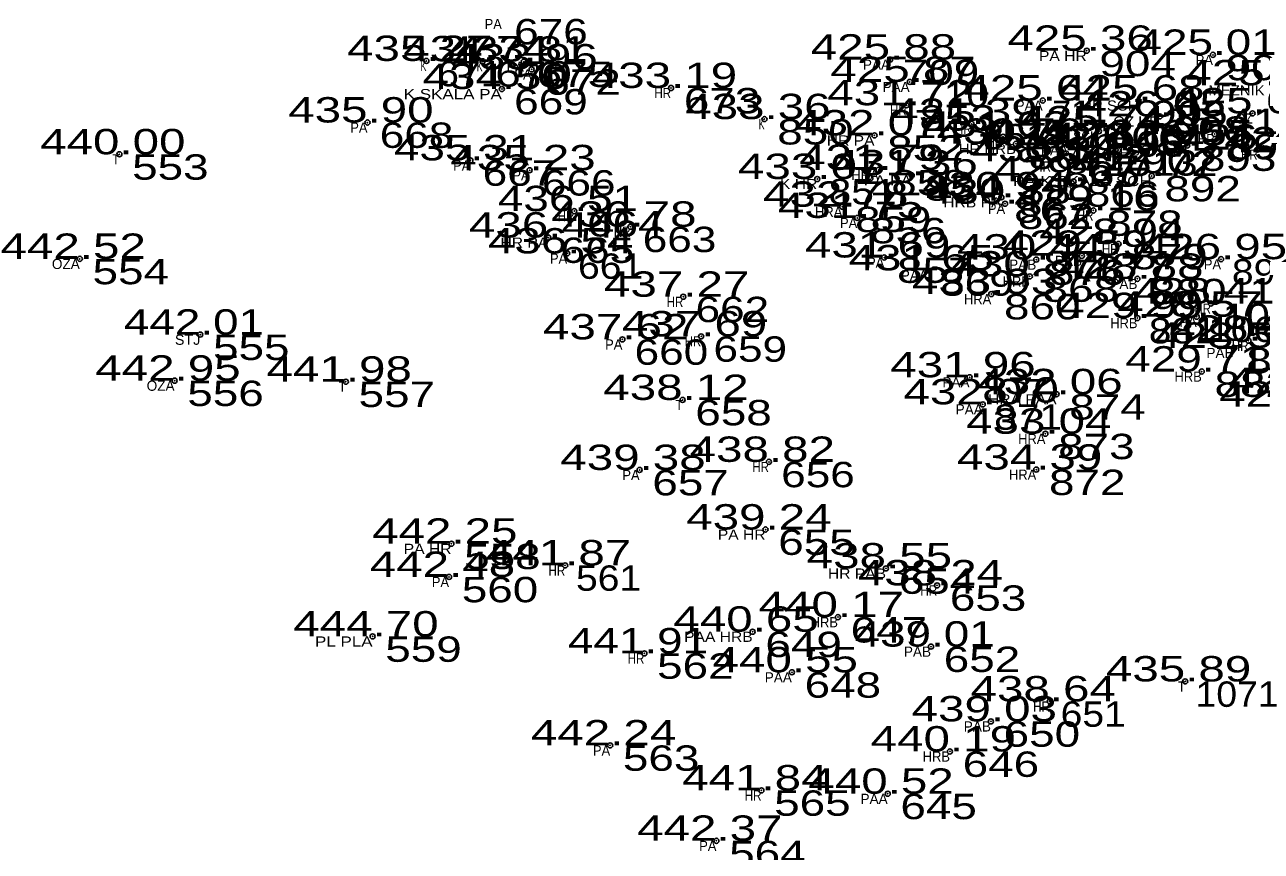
# Model space of a CAD drawing. Extents: x -639390 to -639074, y -1138747 to -1138358.
# Drawn here: x -639157.96 to -639121.42, y -1138697.01 to -1138672.58 of the extents above; entities that cross this region are included whole.
import ezdxf
from ezdxf.enums import TextEntityAlignment as Align

# ---------------------------------------------------------------- set-up
doc = ezdxf.new("R2010")
doc.units = 0
doc.header["$LTSCALE"] = 0.3
doc.header["$PDMODE"] = 32
doc.header["$PDSIZE"] = 0.15
for name, color, linetype in [('11', 7, 'Continuous'), ('12', 7, 'Continuous'), ('13', 7, 'Continuous'), ('57', 7, 'Continuous')]:
    doc.layers.add(name, color=color, linetype=linetype)

msp = doc.modelspace()

# ---------------------------------------------------------------- linework, layer by layer
at = {"layer": '11'}
for p in [(-639146.09, -1138673.65), (-639144.43, -1138673.66), (-639132.39, -1138673.61), (-639126.58, -1138673.35), (-639122.85, -1138673.47), (-639143.21, -1138673.67), (-639142.98, -1138673.9), (-639131.81, -1138674.27), (-639143.86, -1138674.48), (-639138.86, -1138674.45), (-639131.9, -1138674.96), (-639127.88, -1138674.82), (-639125.05, -1138674.82), (-639147.83, -1138675.47), (-639136.1, -1138675.37), (-639124.42, -1138675.29), (-639121.68, -1138675.2), (-639132.85, -1138675.85), (-639129.98, -1138675.51), (-639126.22, -1138675.73), (-639122.8, -1138675.81), (-639129.05, -1138675.89), (-639128.67, -1138676.1), (-639127.13, -1138676.14), (-639123.61, -1138676.15), (-639155.16, -1138676.41), (-639125.65, -1138676.29), (-639125.34, -1138676.22), (-639121.53, -1138676.27), (-639144.79, -1138676.59), (-639143.04, -1138676.88), (-639132.73, -1138676.87), (-639127.64, -1138676.62), (-639134.54, -1138677.14), (-639131.75, -1138677.03), (-639126.97, -1138677.21), (-639124.66, -1138677.05), (-639133.8, -1138677.96), (-639129.1, -1138677.68), (-639128.99, -1138677.87), (-639141.72, -1138678.09), (-639133.36, -1138678.29), (-639126.38, -1138678.07), (-639140.06, -1138678.55), (-639142.49, -1138678.87), (-639125.64, -1138679.06), (-639156.33, -1138679.5), (-639141.93, -1138679.34), (-639132.56, -1138679.46), (-639126.72, -1138679.41), (-639131.27, -1138679.84), (-639128.07, -1138679.52), (-639122.61, -1138679.51), (-639128.26, -1138680.02), (-639125.08, -1138680.09), (-639129.4, -1138680.54), (-639138.5, -1138680.62), (-639122.91, -1138680.82), (-639125.08, -1138681.25), (-639123.33, -1138681.21), (-639152.77, -1138681.74), (-639140.3, -1138681.88), (-639137.97, -1138681.79), (-639121.8, -1138681.92), (-639122.24, -1138682.13), (-639153.53, -1138683.1), (-639148.47, -1138683.13), (-639130.04, -1138683), (-639123.18, -1138682.83), (-639127.47, -1138683.5), (-639138.52, -1138683.67), (-639129.65, -1138683.8), (-639127.8, -1138684.67), (-639135.97, -1138685.5), (-639139.79, -1138685.74), (-639128.07, -1138685.73), (-639136.07, -1138687.5), (-639145.35, -1138687.92), (-639141.99, -1138688.56), (-639145.42, -1138688.9), (-639132.51, -1138688.65), (-639131, -1138689.15), (-639133.93, -1138690.09), (-639147.68, -1138690.66), (-639136.45, -1138690.52), (-639139.65, -1138691.16), (-639131.18, -1138690.96), (-639135.29, -1138691.72), (-639123.67, -1138691.99), (-639127.67, -1138692.58), (-639129.41, -1138693.17), (-639140.66, -1138693.88), (-639130.62, -1138694.06), (-639136.19, -1138695.21), (-639132.46, -1138695.31), (-639137.52, -1138696.7)]:
    msp.add_point(p, dxfattribs=at)

# ---------------------------------------------------------------- texts
at = {"layer": '12'}
for s, width, p in [('425.88 ', 1.4, (-639132.39, -1138673.61)), ('425.36 ', 1.4, (-639126.579, -1138673.35)), ('425.01 ', 1.35, (-639122.849, -1138673.47)), ('435.27 ', 1.4, (-639146.09, -1138673.65)), ('434.74 ', 1.4, (-639144.43, -1138673.66)), ('433.81 ', 1.35, (-639143.209, -1138673.67)), ('433.96 ', 1.4, (-639142.979, -1138673.9)), ('425.87 ', 1.4, (-639131.81, -1138674.27)), ('434.50 ', 1.4, (-639143.86, -1138674.48)), ('433.19 ', 1.4, (-639138.86, -1138674.45)), ('425.18 ', 1.4, (-639121.32, -1138674.37)), ('431.72 ', 1.4, (-639131.9, -1138674.96)), ('425.64 ', 1.4, (-639127.88, -1138674.82)), ('425.68 ', 1.4, (-639125.05, -1138674.82)), ('433.36 ', 1.4, (-639136.099, -1138675.37)), ('426.05 ', 1.4, (-639124.42, -1138675.29)), ('425.62 ', 1.4, (-639121.68, -1138675.2)), ('435.90 ', 1.4, (-639147.83, -1138675.47)), ('431.39 ', 1.4, (-639129.98, -1138675.51)), ('425.74 ', 1.4, (-639126.22, -1138675.73)), ('432.07 ', 1.4, (-639132.85, -1138675.85)), ('431.03 ', 1.4, (-639129.05, -1138675.89)), ('430.76 ', 1.4, (-639128.669, -1138676.1)), ('425.78 ', 1.4, (-639127.13, -1138676.14)), ('426.55 ', 1.4, (-639123.61, -1138676.15)), ('426.41 ', 1.35, (-639122.799, -1138675.81)), ('440.00 ', 1.4, (-639155.16, -1138676.41)), ('426.06 ', 1.4, (-639125.649, -1138676.29)), ('426.09 ', 1.4, (-639125.34, -1138676.22)), ('426.49 ', 1.4, (-639121.53, -1138676.27)), ('425.63 ', 1.4, (-639120.17, -1138676.35)), ('435.31 ', 1.35, (-639144.789, -1138676.59)), ('435.23 ', 1.4, (-639143.04, -1138676.88)), ('431.79 ', 1.4, (-639132.73, -1138676.87)), ('430.14 ', 1.4, (-639127.64, -1138676.62)), ('433.07 ', 1.4, (-639134.54, -1138677.14)), ('431.36 ', 1.4, (-639131.749, -1138677.03)), ('429.67 ', 1.4, (-639126.97, -1138677.21)), ('426.72 ', 1.4, (-639124.66, -1138677.05)), ('432.78 ', 1.4, (-639133.8, -1138677.96)), ('430.94 ', 1.4, (-639129.1, -1138677.68)), ('430.88 ', 1.4, (-639128.99, -1138677.87)), ('436.51 ', 1.35, (-639141.719, -1138678.09)), ('431.75 ', 1.4, (-639133.36, -1138678.29)), ('429.16 ', 1.4, (-639126.379, -1138678.07)), ('436.78 ', 1.4, (-639140.06, -1138678.55)), ('436.44 ', 1.4, (-639142.49, -1138678.87)), ('428.94 ', 1.4, (-639125.64, -1138679.06)), ('436.54 ', 1.4, (-639141.93, -1138679.34)), ('431.69 ', 1.4, (-639132.56, -1138679.46)), ('429.59 ', 1.4, (-639126.72, -1138679.41)), ('442.52 ', 1.4, (-639156.33, -1138679.5)), ('430.44 ', 1.4, (-639128.07, -1138679.52)), ('426.95 ', 1.4, (-639122.61, -1138679.51)), ('431.65 ', 1.4, (-639131.27, -1138679.84)), ('430.87 ', 1.4, (-639128.26, -1138680.02)), ('428.88 ', 1.4, (-639125.08, -1138680.09)), ('433.93 ', 1.4, (-639129.4, -1138680.54)), ('437.27 ', 1.4, (-639138.5, -1138680.62)), ('428.41 ', 1.35, (-639122.909, -1138680.82)), ('429.99 ', 1.4, (-639125.08, -1138681.25)), ('428.57 ', 1.4, (-639123.33, -1138681.21)), ('442.01 ', 1.35, (-639152.769, -1138681.74)), ('437.62 ', 1.4, (-639140.3, -1138681.88)), ('437.69 ', 1.4, (-639137.97, -1138681.79)), ('428.40 ', 1.4, (-639121.8, -1138681.92)), ('426.87 ', 1.4, (-639119.17, -1138681.79)), ('428.58 ', 1.4, (-639122.24, -1138682.13)), ('442.95 ', 1.4, (-639153.53, -1138683.1)), ('431.96 ', 1.4, (-639130.039, -1138683)), ('429.71 ', 1.35, (-639123.179, -1138682.83)), ('441.98 ', 1.4, (-639148.47, -1138683.13)), ('428.43 ', 1.4, (-639120.05, -1138683.47)), ('438.12 ', 1.4, (-639138.52, -1138683.67)), ('432.07 ', 1.4, (-639129.65, -1138683.8)), ('432.06 ', 1.4, (-639127.469, -1138683.5)), ('428.68 ', 1.4, (-639120.32, -1138683.87)), ('433.04 ', 1.4, (-639127.8, -1138684.67)), ('438.82 ', 1.4, (-639135.97, -1138685.5)), ('439.38 ', 1.4, (-639139.79, -1138685.74)), ('434.39 ', 1.4, (-639128.07, -1138685.73)), ('439.24 ', 1.4, (-639136.07, -1138687.5)), ('442.25 ', 1.4, (-639145.35, -1138687.92)), ('441.87 ', 1.4, (-639141.99, -1138688.56)), ('442.48 ', 1.4, (-639145.42, -1138688.9)), ('438.55 ', 1.4, (-639132.51, -1138688.65)), ('438.24 ', 1.4, (-639131, -1138689.15)), ('440.17 ', 1.4, (-639133.93, -1138690.09)), ('444.70 ', 1.4, (-639147.68, -1138690.66)), ('440.65 ', 1.4, (-639136.45, -1138690.52)), ('439.01 ', 1.35, (-639131.179, -1138690.96)), ('441.91 ', 1.35, (-639139.649, -1138691.16)), ('440.55 ', 1.4, (-639135.29, -1138691.72)), ('435.89 ', 1.4, (-639123.67, -1138691.99)), ('438.64 ', 1.4, (-639127.67, -1138692.58)), ('439.03 ', 1.4, (-639129.41, -1138693.17)), ('442.24 ', 1.4, (-639140.66, -1138693.88)), ('440.19 ', 1.4, (-639130.62, -1138694.06)), ('441.84 ', 1.4, (-639136.19, -1138695.21)), ('440.52 ', 1.4, (-639132.46, -1138695.31)), ('442.37 ', 1.4, (-639137.52, -1138696.7))]:
    msp.add_text(s, height=0.75, dxfattribs=dict(at, width=width)).set_placement(p, align=Align.CENTER)
at = {"layer": '13'}
for s, width, p in [(' 676', 1.3, (-639143.86, -1138673.16)), (' 904', 1.35, (-639126.58, -1138674.1)), (' 903', 1.35, (-639122.85, -1138674.22)), (' 671', 1.15, (-639146.09, -1138674.4)), (' 670', 1.35, (-639144.43, -1138674.41)), (' 675', 1.35, (-639143.21, -1138674.42)), (' 672', 1.35, (-639142.98, -1138674.65)), (' 709', 1.35, (-639132.39, -1138674.36)), (' 710', 1.2, (-639131.81, -1138675.02)), (' 669', 1.3, (-639143.86, -1138675.23)), (' 673', 1.35, (-639138.86, -1138675.2)), (' 853', 1.35, (-639131.9, -1138675.71)), (' 905', 1.35, (-639125.05, -1138675.57)), (' 850', 1.35, (-639136.1, -1138676.12)), (' 908', 1.35, (-639124.42, -1138676.04)), (' 668', 1.3, (-639147.83, -1138676.22)), (' 861', 1.15, (-639129.98, -1138676.26)), (' 906', 1.3, (-639126.22, -1138676.48)), (' 852', 1.35, (-639132.85, -1138676.6)), (' 863', 1.35, (-639129.05, -1138676.64)), (' 864', 1.35, (-639128.67, -1138676.85)), (' 712', 1.2, (-639127.13, -1138676.89)), (' 893', 1.35, (-639123.61, -1138676.9)), (' 894', 1.35, (-639122.8, -1138676.56)), (' 553', 1.35, (-639155.16, -1138677.16)), (' 713', 1.2, (-639125.65, -1138677.04)), (' 907', 1.35, (-639125.34, -1138676.97)), (' 667', 1.3, (-639144.79, -1138677.34)), (' 666', 1.3, (-639143.04, -1138677.63)), (' 858', 1.35, (-639132.73, -1138677.62)), (' 865', 1.35, (-639127.64, -1138677.37)), (' 851', 1.2, (-639134.54, -1138677.89)), (' 854', 1.35, (-639131.75, -1138677.78)), (' 866', 1.3, (-639126.97, -1138677.96)), (' 892', 1.35, (-639124.66, -1138677.8)), (' 859', 1.35, (-639133.8, -1138678.71)), (' 867', 1.35, (-639129.1, -1138678.43)), (' 862', 1.35, (-639128.99, -1138678.62)), (' 664', 1.35, (-639141.72, -1138678.84)), (' 856', 1.35, (-639133.36, -1138679.04)), (' 878', 1.35, (-639126.38, -1138678.82)), (' 663', 1.3, (-639140.06, -1138679.3)), (' 665', 1.3, (-639142.49, -1138679.62)), (' 879', 1.35, (-639125.64, -1138679.81)), (' 661', 1.15, (-639141.93, -1138680.09)), (' 877', 1.35, (-639126.72, -1138680.16)), (' 554', 1.35, (-639156.33, -1138680.25)), (' 857', 1.35, (-639132.56, -1138680.21)), (' 876', 1.35, (-639128.07, -1138680.27)), (' 891', 1.15, (-639122.61, -1138680.26)), (' 869', 1.3, (-639131.27, -1138680.59)), (' 868', 1.35, (-639128.26, -1138680.77)), (' 880', 1.35, (-639125.08, -1138680.84)), (' 662', 1.3, (-639138.5, -1138681.37)), (' 860', 1.35, (-639129.4, -1138681.29)), (' 1068', 1.25, (-639122.91, -1138681.57)), (' 881', 1.2, (-639125.08, -1138682)), (' 1069', 1.2, (-639123.33, -1138681.96)), (' 555', 1.35, (-639152.77, -1138682.49)), (' 660', 1.3, (-639140.3, -1138682.63)), (' 659', 1.3, (-639137.97, -1138682.54)), (' 883', 1.35, (-639122.24, -1138682.88)), (' 870', 1.35, (-639130.04, -1138683.75)), (' 882', 1.35, (-639123.18, -1138683.58)), (' 556', 1.35, (-639153.53, -1138683.85)), (' 557', 1.35, (-639148.47, -1138683.88)), (' 658', 1.35, (-639138.52, -1138684.42)), (' 871', 1.2, (-639129.65, -1138684.55)), (' 874', 1.35, (-639127.47, -1138684.25)), (' 873', 1.35, (-639127.8, -1138685.42)), (' 656', 1.3, (-639135.97, -1138686.25)), (' 657', 1.35, (-639139.79, -1138686.49)), (' 872', 1.35, (-639128.07, -1138686.48)), (' 655', 1.35, (-639136.07, -1138688.25)), (' 558', 1.35, (-639145.35, -1138688.67)), (' 561', 1.15, (-639141.99, -1138689.31)), (' 560', 1.35, (-639145.42, -1138689.65)), (' 654', 1.35, (-639132.51, -1138689.4)), (' 653', 1.35, (-639131, -1138689.9)), (' 647', 1.35, (-639133.93, -1138690.84)), (' 559', 1.35, (-639147.68, -1138691.41)), (' 649', 1.35, (-639136.45, -1138691.27)), (' 652', 1.35, (-639131.18, -1138691.71)), (' 562', 1.35, (-639139.65, -1138691.91)), (' 648', 1.35, (-639135.29, -1138692.47)), (' 1071', 1.1, (-639123.67, -1138692.74)), (' 651', 1.15, (-639127.67, -1138693.33)), (' 650', 1.35, (-639129.41, -1138693.92)), (' 563', 1.35, (-639140.66, -1138694.63)), (' 646', 1.35, (-639130.62, -1138694.81)), (' 565', 1.35, (-639136.19, -1138695.96)), (' 645', 1.35, (-639132.46, -1138696.06)), (' 564', 1.35, (-639137.52, -1138697.45))]:
    msp.add_text(s, height=0.75, dxfattribs=dict(at, width=width)).set_placement(p)
msp.add_text(' 711', height=0.75, dxfattribs=at).set_placement((-639127.88, -1138675.57))
at = {"layer": '57'}
for s, width, p in [('PA', 0.95, (-639143.86, -1138672.71)), ('PA HR', 1.15, (-639126.579, -1138673.65)), ('PA', 0.95, (-639122.85, -1138673.77)), ('K', 0.65, (-639146.089, -1138673.95)), ('K', 0.65, (-639144.429, -1138673.96)), ('PA', 0.95, (-639143.21, -1138673.97)), ('PA', 0.95, (-639142.98, -1138674.2)), ('K SKALA PA', 1.25, (-639143.86, -1138674.78)), ('HR', 0.85, (-639138.859, -1138674.75)), ('MEZNIK', 1.1, (-639121.319, -1138674.67)), ('HR', 0.85, (-639131.899, -1138675.26)), ('HR SCH', 1.1, (-639125.049, -1138675.12)), ('K', 0.65, (-639136.099, -1138675.67)), ('OZ HR', 1.1, (-639124.419, -1138675.59)), ('OZ', 0.9, (-639121.679, -1138675.5)), ('PA', 0.95, (-639147.83, -1138675.77)), ('HR', 0.85, (-639129.979, -1138675.81)), ('SCH', 0.9, (-639126.219, -1138676.03)), ('HR PA', 1.15, (-639132.85, -1138676.15)), ('HR HRB', 1.1, (-639128.669, -1138676.4)), ('HR', 0.85, (-639129.049, -1138676.19)), ('HR', 0.85, (-639122.799, -1138676.11)), ('T', 0.85, (-639155.16, -1138676.71)), ('PAA KA', 1.2, (-639125.65, -1138676.59)), ('SCH', 0.9, (-639125.339, -1138676.52)), ('SCH HR', 1.1, (-639123.609, -1138676.45)), ('HR', 0.85, (-639121.529, -1138676.57)), ('PA', 0.95, (-639144.79, -1138676.89)), ('HRA', 0.95, (-639132.73, -1138677.17)), ('HR', 0.85, (-639127.639, -1138676.92)), ('PA', 0.95, (-639143.04, -1138677.18)), ('K HR', 1.15, (-639134.539, -1138677.44)), ('PA PA', 1.2, (-639131.75, -1138677.33)), ('PA K SKALA SCH', 1.25, (-639124.659, -1138677.35)), ('HR', 0.85, (-639126.969, -1138677.51)), ('HRA', 0.95, (-639133.8, -1138678.26)), ('HRB PA', 1.15, (-639129.1, -1138677.98)), ('PA', 0.95, (-639128.99, -1138678.17)), ('HR', 0.85, (-639141.719, -1138678.39)), ('PA', 0.95, (-639133.36, -1138678.59)), ('HR', 0.85, (-639126.379, -1138678.37)), ('HR', 0.85, (-639140.059, -1138678.85)), ('HR PA', 1.15, (-639142.49, -1138679.17)), ('HR', 0.85, (-639125.639, -1138679.36)), ('PA', 0.95, (-639141.93, -1138679.64)), ('PA', 0.95, (-639132.56, -1138679.76)), ('PA', 0.95, (-639122.61, -1138679.81)), ('HRB', 0.95, (-639128.259, -1138680.32)), ('HR', 0.85, (-639138.499, -1138680.92)), ('HRA', 0.95, (-639129.4, -1138680.84)), ('HR', 0.85, (-639122.909, -1138681.12)), ('HRB', 0.95, (-639125.079, -1138681.55)), ('PA', 0.95, (-639123.33, -1138681.51)), ('STJ', 1.05, (-639152.77, -1138682.04)), ('PA', 0.95, (-639140.3, -1138682.18)), ('HR', 0.85, (-639137.969, -1138682.09)), ('HR', 0.85, (-639121.799, -1138682.22)), ('HRB', 0.95, (-639123.179, -1138683.13)), ('T', 0.85, (-639148.47, -1138683.43)), ('T', 0.85, (-639138.52, -1138683.97)), ('HRA PAA', 1.15, (-639127.47, -1138683.8)), ('HRA', 0.95, (-639127.8, -1138684.97)), ('HR', 0.85, (-639135.969, -1138685.8)), ('PA', 0.95, (-639139.79, -1138686.04)), ('HRA', 0.95, (-639128.07, -1138686.03)), ('PA HR', 1.15, (-639136.069, -1138687.8)), ('PA HR', 1.15, (-639145.349, -1138688.22)), ('HR', 0.85, (-639141.989, -1138688.86)), ('PA', 0.95, (-639145.42, -1138689.2)), ('HR PAB', 1.15, (-639132.509, -1138688.95)), ('HR', 0.85, (-639130.999, -1138689.45)), ('HRB', 0.95, (-639133.929, -1138690.39)), ('PL PLA', 1.25, (-639147.68, -1138690.96)), ('PAA HRB', 1.15, (-639136.449, -1138690.82)), ('HR', 0.85, (-639139.649, -1138691.46)), ('T', 0.85, (-639123.67, -1138692.29)), ('HR', 0.85, (-639127.669, -1138692.88)), ('PA', 0.95, (-639140.66, -1138694.18)), ('HRB', 0.95, (-639130.619, -1138694.36)), ('HR', 0.85, (-639136.189, -1138695.51)), ('PA', 0.95, (-639137.52, -1138697))]:
    msp.add_text(s, height=0.3, dxfattribs=dict(at, width=width)).set_placement(p, align=Align.RIGHT)
for s, p in [('PAA', (-639132.39, -1138673.91)), ('PAA', (-639131.81, -1138674.57)), ('PAA', (-639127.88, -1138675.12)), ('PAA', (-639127.13, -1138676.44)), ('PAB', (-639126.719, -1138679.71)), ('OZA', (-639156.33, -1138679.8)), ('PAB', (-639128.069, -1138679.82)), ('PAA', (-639131.27, -1138680.14)), ('PAB', (-639125.079, -1138680.39)), ('PAB', (-639122.239, -1138682.43)), ('PAA', (-639130.04, -1138683.3)), ('OZA', (-639153.53, -1138683.4)), ('PAA', (-639129.65, -1138684.1)), ('PAB', (-639131.179, -1138691.26)), ('PAA', (-639135.29, -1138692.02)), ('PAB', (-639129.409, -1138693.47)), ('PAA', (-639132.46, -1138695.61))]:
    msp.add_text(s, height=0.3, dxfattribs=at).set_placement(p, align=Align.RIGHT)

doc.saveas('drawing.dxf')
